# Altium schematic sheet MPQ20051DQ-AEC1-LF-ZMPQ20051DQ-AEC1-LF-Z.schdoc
size 127 x 101 mm
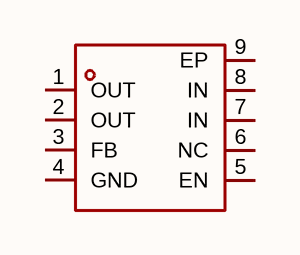
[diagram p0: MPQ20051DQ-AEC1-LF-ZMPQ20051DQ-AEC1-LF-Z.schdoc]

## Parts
U?  mpq20051dq-aec1-lf-z  [TDFN-8_L3.0-W3.0-P0.65-BL-EP]  (value not drawn)

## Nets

Not connected (* = marked no-connect by the designer): U? 1(OUT) 2(OUT) 3(FB) 4(GND) 5(EN) 6(NC) 7(IN) 8(IN) 9(EP)

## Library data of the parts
U? = mpq20051dq-aec1-lf-z: 输出极性:正极;工作电压:5.5V;输出电压:800mV~5V;输出电流:1A;电源纹波抑制比(PSRR):63dB@(1kHz);输出类型:可调;; Manufacturer: MPS(芯源); AddInBom: yes; ModelId: 52cae27a4bb3417391fd5472d998fec7; ModelName: TDFN-8_L3.0-W3.0-H0.8-P0.65; ModelTransform: 118.8974,118.11,0,90,0,0,0,-0.0005,0; Output Configuration: 正极; Voltage - Supply: 5.5V; Output Current: 1A; Voltage Dropout: 280mV@(1A); standby current: 200uA; Noise: 55uVrms; Output Type: 可调; Number of Outputs: 1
